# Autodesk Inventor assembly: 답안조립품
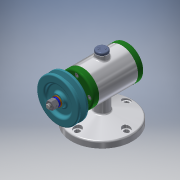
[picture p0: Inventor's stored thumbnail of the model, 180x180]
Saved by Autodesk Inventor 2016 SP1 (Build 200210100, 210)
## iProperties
Created: 2018-12
Part Number: 답안조립품
Material: 일반
Document SubType Name: Assembly
Designer: basic
Author: basic
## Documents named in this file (15)
- C:\Users\basic\Desktop\481208V1013\답안조립품.iam
- C:\Users\basic\Desktop\481208V1013\본체.ipt
- C:\Users\basic\Desktop\481208V1013\베어링 15 x 32 x 9.ipt
- C:\Users\basic\Desktop\481208V1013\앞커버.ipt
- C:\Users\basic\Desktop\481208V1013\뒤커버.ipt
- C:\Users\basic\Desktop\481208V1013\축.ipt
- C:\Users\basic\Desktop\481208V1013\오일 실 15 25 7.ipt
- C:\Users\basic\Desktop\481208V1013\볼트 M4 x 12.ipt
- C:\Users\basic\Desktop\481208V1013\키 3 x 3 x 12.ipt
- C:\Users\basic\Desktop\481208V1013\V벨트풀리.ipt
- C:\Users\basic\Desktop\481208V1013\와셔 8x17.ipt
- C:\Users\basic\Desktop\481208V1013\너트 M8.ipt
- 너트 M8.ipt
- C:\Users\basic\Desktop\481208V1013\스프링와셔 8.ipt
- C:\Users\basic\Desktop\481208V1013\고무캡.ipt
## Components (2 placed, 2 different names)
1. V벨트풀리:1
2. 고무캡:1
